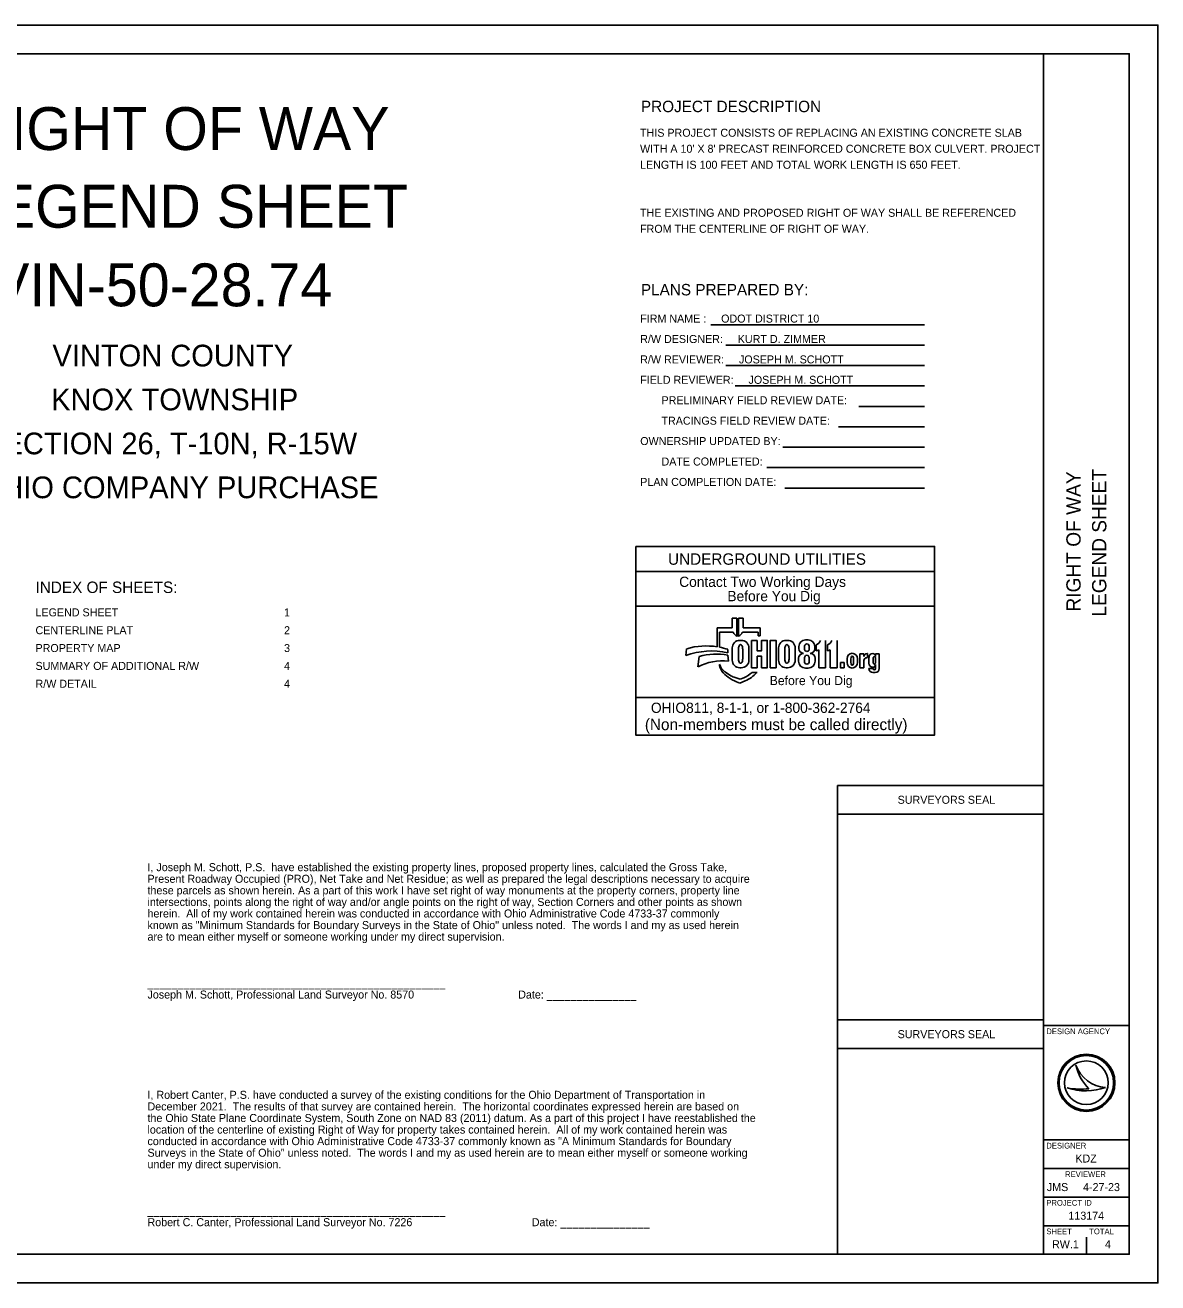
# Model space of a CAD drawing. Extents: x 0 to 34, y 0 to 22.
# Drawn here: x 14.19 to 34, y 0 to 22 of the extents above; entities that cross this region are included whole.
import ezdxf

# ---------------------------------------------------------------- set-up
doc = ezdxf.new("R2010")
doc.units = 0
for name, color, linetype in [('SH_Border', 7, 'Continuous'), ('SH_Cut_Line', 7, 'Continuous'), ('SH_Data', 7, 'Continuous'), ('SH_Text', 7, 'Continuous')]:
    doc.layers.add(name, color=color, linetype=linetype)

msp = doc.modelspace()

# ---------------------------------------------------------------- linework, layer by layer
at = {"layer": 'SH_Border'}
for p, q in [((32, 0.5), (32, 21.5)), ((32, 4.5), (33.5, 4.5)), ((32, 2.5), (33.5, 2.5)), ((32, 2), (33.5, 2)), ((32, 1.5), (33.5, 1.5)), ((32, 1), (33.5, 1))]:
    msp.add_line(p, q, dxfattribs=at)
msp.add_lwpolyline([(1.5, 21.5), (33.5, 21.5), (33.5, 0.5), (1.5, 0.5)], close=True, dxfattribs=at)
at = {"layer": 'SH_Cut_Line'}
msp.add_lwpolyline([(0, 0), (34, 0), (34, 22), (0, 22)], close=True, dxfattribs=at)
at = {"layer": 'SH_Data'}
for p, q in [((26.559, 11.46), (26.296, 11.46)), ((26.296, 11.46), (26.296, 11.125)), ((26.639, 11.626), (26.559, 11.626)), ((26.559, 11.626), (26.559, 11.46)), ((26.639, 11.309), (26.639, 11.626)), ((26.75, 11.626), (26.67, 11.626)), ((26.67, 11.626), (26.67, 11.309)), ((26.75, 11.46), (26.75, 11.626)), ((27.048, 11.46), (26.75, 11.46)), ((27.048, 11.319), (27.048, 11.46)), ((26.334, 11.119), (26.334, 11.383)), ((26.334, 11.383), (26.574, 11.383)), ((26.716, 11.238), (26.691, 11.238)), ((26.735, 11.383), (27.013, 11.383)), ((26.993, 11.237), (26.892, 11.237)), ((26.892, 11.237), (26.892, 10.759)), ((27.013, 11.383), (27.013, 11.319)), ((27.013, 11.319), (27.048, 11.319)), ((27.526, 11.238), (27.502, 11.238)), ((27.887, 11.245), (27.839, 11.245)), ((28.191, 11.237), (28.191, 10.759)), ((28.391, 11.237), (28.391, 10.759)), ((25.761, 11.091), (25.747, 10.974)), ((26.48, 11.023), (26.48, 11.081)), ((26.557, 11.105), (26.557, 10.893)), ((26.666, 10.91), (26.666, 11.092)), ((26.741, 11.092), (26.741, 10.91)), ((26.849, 10.893), (26.849, 11.105)), ((27.368, 11.105), (27.368, 10.893)), ((27.477, 10.91), (27.477, 11.092)), ((27.551, 11.092), (27.551, 10.91)), ((27.66, 10.893), (27.66, 11.105)), ((27.725, 11.131), (27.725, 11.095)), ((27.823, 11.078), (27.823, 11.136)), ((27.904, 11.136), (27.904, 11.078)), ((28.001, 11.095), (28.001, 11.131)), ((28.024, 11.057), (28.024, 11.158)), ((28.073, 10.759), (28.073, 11.071)), ((28.225, 11.057), (28.225, 11.158)), ((28.273, 10.759), (28.273, 11.071)), ((28.86, 11.002), (28.787, 11.002)), ((28.787, 11.002), (28.787, 10.759)), ((28.86, 10.955), (28.86, 11.002)), ((28.921, 11.01), (28.915, 11.01)), ((28.921, 10.936), (28.921, 11.01)), ((29.064, 10.957), (29.064, 11.004)), ((29.064, 11.004), (29.129, 11.004)), ((29.129, 11.004), (29.129, 10.745)), ((25.981, 10.956), (25.959, 10.776)), ((26.333, 10.819), (26.337, 10.792)), ((26.49, 10.873), (26.481, 10.979)), ((26.993, 10.759), (26.993, 10.961)), ((27.719, 10.925), (27.719, 10.874)), ((27.82, 10.865), (27.82, 10.926)), ((27.905, 10.926), (27.905, 10.865)), ((28.007, 10.874), (28.007, 10.925)), ((28.565, 10.85), (28.565, 10.918)), ((28.632, 10.849), (28.632, 10.918)), ((28.68, 10.918), (28.68, 10.849)), ((28.748, 10.918), (28.748, 10.85)), ((28.86, 10.759), (28.86, 10.886)), ((28.909, 10.936), (28.921, 10.936)), ((28.949, 10.837), (28.949, 10.941)), ((29.021, 10.851), (29.021, 10.927)), ((29.064, 10.927), (29.064, 10.851)), ((29.064, 10.745), (29.064, 10.815)), ((26.698, 10.558), (26.609, 10.589)), ((26.691, 10.759), (26.716, 10.759)), ((26.759, 10.585), (26.698, 10.558)), ((26.892, 10.759), (26.993, 10.759)), ((26.991, 10.679), (26.905, 10.679)), ((26.989, 10.676), (26.991, 10.679)), ((27.502, 10.759), (27.526, 10.759)), ((27.84, 10.753), (27.887, 10.753)), ((28.191, 10.759), (28.073, 10.759)), ((28.391, 10.759), (28.273, 10.759)), ((28.787, 10.759), (28.86, 10.759)), ((28.949, 10.745), (29.021, 10.745)), ((29.059, 10.676), (29.019, 10.676)), ((26.633, 10.512), (26.689, 10.488)), ((26.689, 10.488), (26.783, 10.529)), ((30.095, 9.581), (24.87, 9.581)), ((28.4, 8.2), (32, 8.2)), ((28.4, 4.1), (32, 4.1)), ((32.567, 3.81), (32.567, 3.81)), ((32.417, 3.41), (32.417, 3.41)), ((32.75, 3.5), (32.75, 3.5)), ((33.087, 3.419), (33.087, 3.419)), ((32.375, 0.675), (32.375, 0.675)), ((32.75, 0.5), (32.75, 0.8))]:
    msp.add_line(p, q, dxfattribs=at)
for points in [[(24.87, 12.881), (30.095, 12.881), (30.095, 12.441), (24.87, 12.441)], [(24.87, 12.441), (30.095, 12.441), (30.095, 11.836), (24.87, 11.836)], [(24.87, 11.836), (30.095, 11.836), (30.095, 10.241), (24.87, 10.241)], [(28.449, 10.849), (28.515, 10.849), (28.515, 10.759), (28.449, 10.759)], [(24.87, 10.241), (30.095, 10.241), (30.095, 9.581), (24.87, 9.581)], [(28.4, 8.7), (32, 8.7), (32, 4.6), (28.4, 4.6)], [(28.4, 4.6), (32, 4.6), (32, 0.5), (28.4, 0.5)]]:
    msp.add_lwpolyline(points, close=True, dxfattribs=at)
for points in [[(26.993, 10.961), (27.07, 10.961), (27.07, 10.759), (27.171, 10.759), (27.171, 11.237), (27.07, 11.237), (27.07, 11.057), (26.993, 11.057), (26.993, 11.237)], [(27.222, 10.759), (27.325, 10.759), (27.325, 11.237), (27.222, 11.237), (27.222, 10.759)], [(27.805, 11.011), (27.805, 11.011)], [(27.921, 11.011), (27.921, 11.011)]]:
    msp.add_lwpolyline(points, dxfattribs=at)
for radius in [0.5, 0.477, 0.477, 0.382]:
    msp.add_circle((32.75, 3.5), radius, dxfattribs=at)
for centre, radius, start, end in [((26.691, 11.105), 0.134, 90, 180), ((26.711, 11.438), 0.147, 201.9296, 240.7469), ((26.598, 11.438), 0.147, 299.2531, 338.0704), ((26.716, 11.105), 0.134, 0, 90), ((27.502, 11.105), 0.134, 90, 180), ((27.526, 11.105), 0.134, 0, 90), ((27.839, 11.131), 0.114, 90, 180), ((27.887, 11.131), 0.114, 0, 90), ((27.974, 11.281), 0.132, 292.5572, 340.7355), ((28.174, 11.281), 0.132, 292.5572, 340.7355), ((26.199, 9.721), 1.332, 77.8238, 109.8274), ((26.105, 9.917), 1.224, 81.0007, 106.3144), ((26.105, 9.917), 1.224, 72.1402, 79.2074), ((27.805, 10.925), 0.0865, 90, 180), ((27.808, 11.095), 0.0837, 180, 268.1442), ((27.918, 11.095), 0.0837, 272.2058, 0), ((27.921, 10.925), 0.0865, 0, 90), ((28.013, 11.188), 0.132, 275.1733, 297.0931), ((28.213, 11.188), 0.132, 275.1733, 297.0931), ((28.661, 10.918), 0.0956, 92.5886, 180), ((28.652, 10.918), 0.0956, 0, 87.4114), ((28.915, 10.955), 0.0548, 90, 180), ((29.018, 10.941), 0.0686, 92.6865, 180), ((29.012, 10.957), 0.0524, 0, 86.9262), ((26.388, 9.929), 0.95, 83.8248, 116.8021), ((26.28, 9.904), 1.094, 79.44, 105.8467), ((26.613, 10.927), 0.3, 201.0457, 232.5314), ((26.548, 10.828), 0.214, 189.6817, 216.0884), ((26.691, 10.893), 0.134, 180, 270), ((26.716, 10.893), 0.134, 270, 0), ((27.502, 10.893), 0.134, 180, 270), ((27.526, 10.893), 0.134, 270, 0), ((27.84, 10.874), 0.121, 180, 270), ((27.887, 10.874), 0.121, 270, 0), ((28.661, 10.85), 0.0956, 180, 267.4114), ((28.652, 10.85), 0.0956, 272.5886, 0), ((28.909, 10.886), 0.0493, 90, 180), ((29.018, 10.837), 0.0692, 180, 265.7132), ((29.017, 10.815), 0.0467, 264.7825, 0), ((26.748, 10.974), 0.461, 216.0884, 235.7167), ((26.9, 11.302), 0.773, 232.5314, 241.794), ((26.997, 11.339), 0.903, 235.7167, 246.2325), ((26.773, 11.065), 0.504, 241.794, 250.9821), ((26.545, 11.078), 0.538, 293.4582, 312.0712), ((26.545, 11.078), 0.599, 293.4582, 317.8286), ((29.019, 10.745), 0.0699, 180, 270), ((29.059, 10.745), 0.0699, 270, 0), ((33.116, 3.998), 0.58, 198.9257, 198.9319), ((33.347, 3.97), 0.796, 191.6379, 191.6421), ((33.116, 3.998), 0.58, 198.9319, 267.1657), ((33.347, 3.97), 0.796, 191.6421, 226.0947), ((32.739, 4.37), 1.013, 251.4576, 290.0832), ((32.648, 4.654), 1.266, 259.4964, 259.4995), ((32.739, 4.37), 1.013, 251.4527, 251.4576), ((32.648, 4.654), 1.266, 259.4995, 276.6672)]:
    msp.add_arc(centre, radius, start, end, dxfattribs=at)
for centre, major_axis, ratio, start_param, end_param in [((26.703, 11.092), (0, 0.0723), 0.514403, 4.712389, 7.853982), ((27.514, 11.092), (0, 0.0723), 0.514403, 4.712389, 7.853982), ((27.864, 11.136), (0.0404, 0), 0.969373, 0, 3.141593), ((27.864, 11.078), (0.0404, 0), 0.818453, 3.141593, 6.283185), ((26.703, 10.91), (0, 0.0723), 0.514403, 1.570796, 4.712389), ((27.514, 10.91), (0, 0.0723), 0.514403, 1.570796, 4.712389), ((27.862, 10.926), (0, 0.0535), 0.794529, 4.712389, 7.853982), ((27.862, 10.865), (0.0425, 0), 0.959837, 3.141593, 6.283185), ((28.656, 10.918), (0, 0.0434), 0.553236, 4.712389, 7.853982), ((28.656, 10.849), (0, 0.046), 0.522014, 1.570796, 4.712389), ((29.043, 10.927), (0, 0.0275), 0.777179, 4.712389, 7.853982), ((29.043, 10.851), (0, 0.0275), 0.777179, 1.570796, 4.712389), ((29.043, 10.745), (0.0214, 0), 0.959012, 3.141593, 6.283185)]:
    msp.add_ellipse(centre, major_axis=major_axis, ratio=ratio, start_param=start_param, end_param=end_param, dxfattribs=at)
at = {"layer": 'SH_Text'}
for p, q in [((26.181, 16.76), (29.918, 16.76)), ((26.445, 16.403), (29.918, 16.403)), ((26.445, 16.046), (29.918, 16.046)), ((26.609, 15.689), (29.918, 15.689)), ((28.773, 15.331), (29.918, 15.331)), ((28.415, 14.974), (29.918, 14.974)), ((27.445, 14.617), (29.918, 14.617)), ((27.16, 14.26), (29.918, 14.26)), ((27.475, 13.903), (29.918, 13.903))]:
    msp.add_line(p, q, dxfattribs=at)

# ---------------------------------------------------------------- texts
at = {"layer": 'SH_Data'}
for s, height, p in [('RIGHT OF WAY', 0.75, (13.21, 19.816)), ('LEGEND SHEET', 0.75, (13.141, 18.457)), ('VIN-50-28.74', 0.75, (13.599, 17.082)), ('VINTON COUNTY', 0.38, (14.671, 16.03)), ('KNOX TOWNSHIP', 0.38, (14.648, 15.262)), ('SECTION 26, T-10N, R-15W', 0.38, (13.477, 14.493)), ('OHIO COMPANY PURCHASE', 0.38, (13.398, 13.725)), ('UNDERGROUND UTILITIES', 0.2, (25.435, 12.561)), ('Contact Two Working Days', 0.18, (25.63, 12.173)), ('INDEX OF SHEETS:', 0.2, (14.375, 12.067)), ('Before You Dig', 0.18, (26.473, 11.923)), ('LEGEND SHEET', 0.14, (14.375, 11.658)), ('1', 0.14, (18.721, 11.658)), ('CENTERLINE PLAT', 0.14, (14.375, 11.346)), ('2', 0.14, (18.721, 11.346)), ('PROPERTY MAP', 0.14, (14.375, 11.034)), ('3', 0.14, (18.721, 11.034)), ('SUMMARY OF ADDITIONAL R/W', 0.14, (14.375, 10.722)), ('4', 0.14, (18.721, 10.722)), ('Before You Dig', 0.15972, (27.213, 10.456)), ('R/W DETAIL', 0.14, (14.375, 10.41)), ('4', 0.14, (18.721, 10.41)), ('OHIO811, 8-1-1, or 1-800-362-2764', 0.18, (25.136, 9.969)), ('(Non-members must be called directly)', 0.2, (25.03, 9.668)), ('SURVEYORS SEAL', 0.14, (29.45, 8.38)), ('SURVEYORS SEAL', 0.14, (29.45, 4.28)), ('DESIGN AGENCY', 0.1, (32.05, 4.35)), ('DESIGNER', 0.1, (32.05, 2.35)), ('KDZ', 0.14, (32.557, 2.105)), ('REVIEWER', 0.1, (32.378, 1.85)), ('JMS', 0.14, (32.059, 1.605)), ('4-27-23', 0.14, (32.692, 1.605)), ('PROJECT ID', 0.1, (32.05, 1.35)), ('113174', 0.14, (32.436, 1.105)), ('SHEET', 0.1, (32.05, 0.85)), ('TOTAL', 0.1, (32.8, 0.85)), ('RW.1', 0.14, (32.15, 0.605)), ('4', 0.14, (33.075, 0.605))]:
    msp.add_text(s, height=height, dxfattribs=at).set_placement(p)
for s, p in [('RIGHT OF WAY', (32.65, 11.743)), ('LEGEND SHEET', (33.1, 11.654))]:
    msp.add_text(s, height=0.25, rotation=90, dxfattribs=at).set_placement(p)
at = {"layer": 'SH_Text'}
for s, height, p in [('PROJECT DESCRIPTION', 0.2, (24.961, 20.478)), ('THIS PROJECT CONSISTS OF REPLACING AN EXISTING CONCRETE SLAB ', 0.14, (24.946, 20.048)), ("WITH A 10' X 8' PRECAST REINFORCED CONCRETE BOX CULVERT. PROJECT ", 0.14, (24.946, 19.768)), ('LENGTH IS 100 FEET AND TOTAL WORK LENGTH IS 650 FEET.', 0.14, (24.946, 19.488)), ('THE EXISTING AND PROPOSED RIGHT OF WAY SHALL BE REFERENCED ', 0.14, (24.946, 18.648)), ('FROM THE CENTERLINE OF RIGHT OF WAY.', 0.14, (24.946, 18.368)), ('PLANS PREPARED BY:', 0.2, (24.961, 17.273)), ('FIRM NAME :     ODOT DISTRICT 10', 0.14, (24.949, 16.797)), ('R/W DESIGNER:     KURT D. ZIMMER', 0.14, (24.949, 16.44)), ('R/W REVIEWER:     JOSEPH M. SCHOTT', 0.14, (24.949, 16.083)), ('FIELD REVIEWER:     JOSEPH M. SCHOTT', 0.14, (24.949, 15.726)), ('PRELIMINARY FIELD REVIEW DATE:', 0.14, (25.321, 15.369)), ('TRACINGS FIELD REVIEW DATE:           ', 0.14, (25.321, 15.011)), ('OWNERSHIP UPDATED BY:', 0.14, (24.949, 14.655)), ('DATE COMPLETED:', 0.14, (25.321, 14.297)), ('PLAN COMPLETION DATE:', 0.14, (24.949, 13.94)), ('I, Joseph M. Schott, P.S.  have established the existing property lines, proposed property lines, calculated the Gross Take, ', 0.14, (16.333, 7.201)), ('Present Roadway Occupied (PRO), Net Take and Net Residue; as well as prepared the legal descriptions necessary to acquire ', 0.14, (16.333, 6.998)), ('these parcels as shown herein. As a part of this work I have set right of way monuments at the property corners, property line ', 0.14, (16.333, 6.796)), ('intersections, points along the right of way and/or angle points on the right of way, Section Corners and other points as shown ', 0.14, (16.333, 6.593)), ('herein.  All of my work contained herein was conducted in accordance with Ohio Administrative Code 4733-37 commonly ', 0.14, (16.333, 6.391)), ('known as "Minimum Standards for Boundary Surveys in the State of Ohio" unless noted.  The words I and my as used herein ', 0.14, (16.333, 6.188)), ('are to mean either myself or someone working under my direct supervision.', 0.14, (16.333, 5.986)), ('__________________________________________________', 0.14, (16.333, 5.176)), ('Joseph M. Schott, Professional Land Surveyor No. 8570                                   Date: _______________                  ', 0.14, (16.333, 4.973)), ('I, Robert Canter, P.S. have conducted a survey of the existing conditions for the Ohio Department of Transportation in ', 0.14, (16.333, 3.219)), ('December 2021.  The results of that survey are contained herein.  The horizontal coordinates expressed herein are based on ', 0.14, (16.333, 3.016)), ('the Ohio State Plane Coordinate System, South Zone on NAD 83 (2011) datum. As a part of this project I have reestablished the ', 0.14, (16.333, 2.814)), ('location of the centerline of existing Right of Way for property takes contained herein.  All of my work contained herein was ', 0.14, (16.333, 2.611)), ('conducted in accordance with Ohio Administrative Code 4733-37 commonly known as "A Minimum Standards for Boundary ', 0.14, (16.333, 2.409)), ('Surveys in the State of Ohio" unless noted.  The words I and my as used herein are to mean either myself or someone working ', 0.14, (16.333, 2.206)), ('under my direct supervision.', 0.14, (16.333, 2.004)), ('__________________________________________________', 0.14, (16.333, 1.194)), ('Robert C. Canter, Professional Land Surveyor No. 7226                           ', 0.14, (16.333, 0.991)), ('Date: _______________ ', 0.14, (23.053, 0.991))]:
    msp.add_text(s, height=height, dxfattribs=at).set_placement(p)

doc.saveas('drawing.dxf')
